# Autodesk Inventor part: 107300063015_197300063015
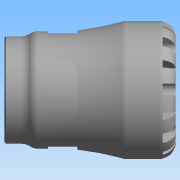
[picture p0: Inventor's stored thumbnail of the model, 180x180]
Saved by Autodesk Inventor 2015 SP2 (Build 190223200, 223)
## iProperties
Created: 2016-12
Part Number: 107300063015_197300063015
Material: Generic
Description: PLASSON FEMALE INTEGRAL BRASS THREAD 63X1.1/2" SERIES 1
Document SubType Name: Modeling
Designer: KIM
Density: 1 g/cm^3
Appearance: Default
Author: KIM
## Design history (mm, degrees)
derived "1073.ipt"
feature "Solid1::1073.ipt"
tag "TaggingFeature1"
body "Solid1"
other parameters: "d0" = 128, "d1" = 38.64, "d2" = 63, "d3" = 78.75, "d4" = 103, "d6" = 92, "d8" = 87.55, "d13" = 9.7, "d14" = 9.7, "d15" = 0, "d17" = 360 deg, "d19" = 8 deg, "d20" = 1.26, "d21" = 1.26, "d22" = 8 deg, "d24" = 0, "d26" = 360 deg, "d32" = 10.3, "d33" = 10.3, "d39" = 1.34535, "d42" = 44.845, "d43" = 80.34, "d46" = 5.25, "d47" = 21, "d48" = 42.60275, "d50" = 4.95, "d51" = 1.03, "d54" = 22.05, "d55" = 13.86, "d57" = 19.012, "d58" = 0, "d68" = 360 deg, "d72" = 1.26, "d74" = 0, "d76" = 18.7425, "d_" = 63, "E_" = 103, "H_" = 128, "l_" = 92, "G_" = 44.845, "l_2" = 21, "d9" = 12.125, "d11" = 103, "d12" = 78.75, "d49" = 15
